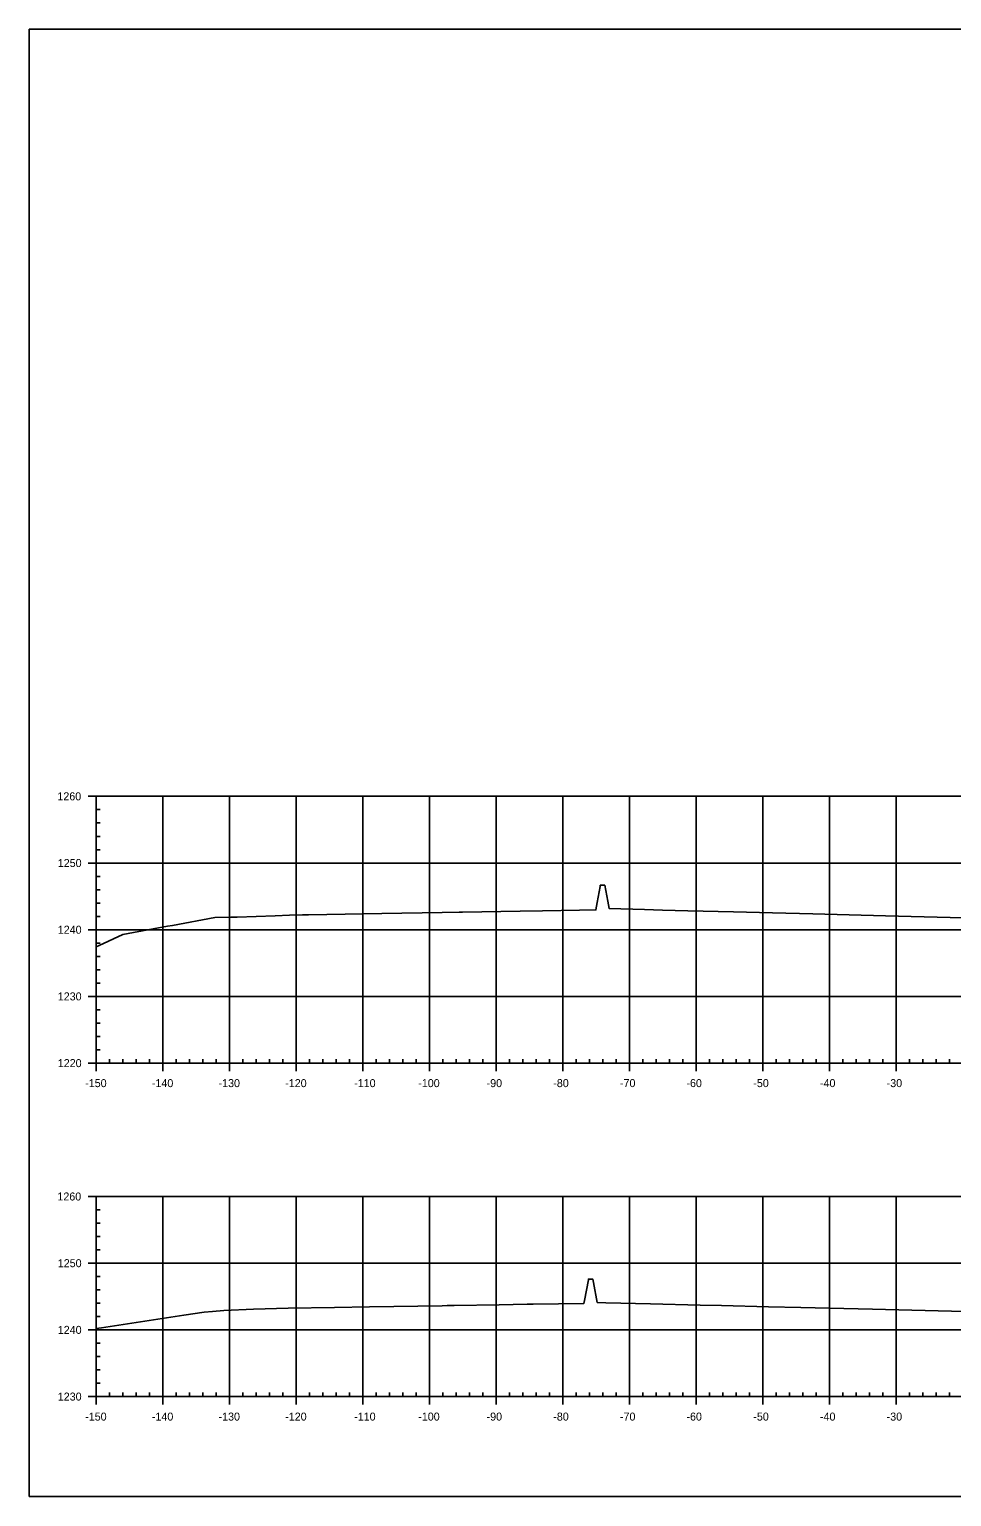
# Model space of a CAD drawing. Extents: x 659657 to 668193, y 633084 to 648639.
# Drawn here: x 667852.5 to 667990.8, y 643502.4 to 643722.4 of the extents above; entities that cross this region are included whole.
import ezdxf

# ---------------------------------------------------------------- set-up
doc = ezdxf.new("R2010")
doc.units = 0
for name, color, linetype in [('R_Axis', 7, 'Continuous'), ('R_Axis Annot', 7, 'Continuous'), ('R_Exist Surface', 7, 'Continuous'), ('R_Grid', 7, 'Continuous'), ('T_SIGNAL CONTROL CABINET', 7, 'Continuous')]:
    doc.layers.add(name, color=color, linetype=linetype)

msp = doc.modelspace()

# ---------------------------------------------------------------- linework, layer by layer
at = {"layer": 'R_Axis'}
for p, q in [((667861.31, 643607.39), (667863.71, 643607.39)), ((667862.51, 643567.39), (667862.51, 643607.39)), ((667862.51, 643605.39), (667863.11, 643605.39)), ((667862.51, 643603.39), (667863.11, 643603.39)), ((667862.51, 643601.39), (667863.11, 643601.39)), ((667862.51, 643599.39), (667863.11, 643599.39)), ((667861.31, 643597.39), (667863.71, 643597.39)), ((667862.51, 643595.39), (667863.11, 643595.39)), ((667862.51, 643593.39), (667863.11, 643593.39)), ((667862.51, 643591.39), (667863.11, 643591.39)), ((667862.51, 643589.39), (667863.11, 643589.39)), ((667861.31, 643587.39), (667863.71, 643587.39)), ((667862.51, 643585.39), (667863.11, 643585.39)), ((667862.51, 643583.39), (667863.11, 643583.39)), ((667862.51, 643581.39), (667863.11, 643581.39)), ((667862.51, 643579.39), (667863.11, 643579.39)), ((667861.31, 643577.39), (667863.71, 643577.39)), ((667862.51, 643575.39), (667863.11, 643575.39)), ((667862.51, 643573.39), (667863.11, 643573.39)), ((667862.51, 643571.39), (667863.11, 643571.39)), ((667862.51, 643569.39), (667863.11, 643569.39)), ((667862.51, 643566.19), (667862.51, 643568.59)), ((667872.51, 643566.19), (667872.51, 643568.59)), ((667882.51, 643566.19), (667882.51, 643568.59)), ((667892.51, 643566.19), (667892.51, 643568.59)), ((667902.51, 643566.19), (667902.51, 643568.59)), ((667912.51, 643566.19), (667912.51, 643568.59)), ((667922.51, 643566.19), (667922.51, 643568.59)), ((667932.51, 643566.19), (667932.51, 643568.59)), ((667942.51, 643566.19), (667942.51, 643568.59)), ((667952.51, 643566.19), (667952.51, 643568.59)), ((667962.51, 643566.19), (667962.51, 643568.59)), ((667972.51, 643566.19), (667972.51, 643568.59)), ((667982.51, 643566.19), (667982.51, 643568.59)), ((667861.31, 643567.39), (667863.71, 643567.39)), ((667862.51, 643567.39), (668162.51, 643567.39)), ((667864.51, 643567.39), (667864.51, 643567.99)), ((667866.51, 643567.39), (667866.51, 643567.99)), ((667868.51, 643567.39), (667868.51, 643567.99)), ((667870.51, 643567.39), (667870.51, 643567.99)), ((667874.51, 643567.39), (667874.51, 643567.99)), ((667876.51, 643567.39), (667876.51, 643567.99)), ((667878.51, 643567.39), (667878.51, 643567.99)), ((667880.51, 643567.39), (667880.51, 643567.99)), ((667884.51, 643567.39), (667884.51, 643567.99)), ((667886.51, 643567.39), (667886.51, 643567.99)), ((667888.51, 643567.39), (667888.51, 643567.99)), ((667890.51, 643567.39), (667890.51, 643567.99)), ((667894.51, 643567.39), (667894.51, 643567.99)), ((667896.51, 643567.39), (667896.51, 643567.99)), ((667898.51, 643567.39), (667898.51, 643567.99)), ((667900.51, 643567.39), (667900.51, 643567.99)), ((667904.51, 643567.39), (667904.51, 643567.99)), ((667906.51, 643567.39), (667906.51, 643567.99)), ((667908.51, 643567.39), (667908.51, 643567.99)), ((667910.51, 643567.39), (667910.51, 643567.99)), ((667914.51, 643567.39), (667914.51, 643567.99)), ((667916.51, 643567.39), (667916.51, 643567.99)), ((667918.51, 643567.39), (667918.51, 643567.99)), ((667920.51, 643567.39), (667920.51, 643567.99)), ((667924.51, 643567.39), (667924.51, 643567.99)), ((667926.51, 643567.39), (667926.51, 643567.99)), ((667928.51, 643567.39), (667928.51, 643567.99)), ((667930.51, 643567.39), (667930.51, 643567.99)), ((667934.51, 643567.39), (667934.51, 643567.99)), ((667936.51, 643567.39), (667936.51, 643567.99)), ((667938.51, 643567.39), (667938.51, 643567.99)), ((667940.51, 643567.39), (667940.51, 643567.99)), ((667944.51, 643567.39), (667944.51, 643567.99)), ((667946.51, 643567.39), (667946.51, 643567.99)), ((667948.51, 643567.39), (667948.51, 643567.99)), ((667950.51, 643567.39), (667950.51, 643567.99)), ((667954.51, 643567.39), (667954.51, 643567.99)), ((667956.51, 643567.39), (667956.51, 643567.99)), ((667958.51, 643567.39), (667958.51, 643567.99)), ((667960.51, 643567.39), (667960.51, 643567.99)), ((667964.51, 643567.39), (667964.51, 643567.99)), ((667966.51, 643567.39), (667966.51, 643567.99)), ((667968.51, 643567.39), (667968.51, 643567.99)), ((667970.51, 643567.39), (667970.51, 643567.99)), ((667974.51, 643567.39), (667974.51, 643567.99)), ((667976.51, 643567.39), (667976.51, 643567.99)), ((667978.51, 643567.39), (667978.51, 643567.99)), ((667980.51, 643567.39), (667980.51, 643567.99)), ((667984.51, 643567.39), (667984.51, 643567.99)), ((667986.51, 643567.39), (667986.51, 643567.99)), ((667988.51, 643567.39), (667988.51, 643567.99)), ((667990.51, 643567.39), (667990.51, 643567.99)), ((667861.31, 643547.39), (667863.71, 643547.39)), ((667862.51, 643517.39), (667862.51, 643547.39)), ((667862.51, 643545.39), (667863.11, 643545.39)), ((667862.51, 643543.39), (667863.11, 643543.39)), ((667862.51, 643541.39), (667863.11, 643541.39)), ((667862.51, 643539.39), (667863.11, 643539.39)), ((667861.31, 643537.39), (667863.71, 643537.39)), ((667862.51, 643535.39), (667863.11, 643535.39)), ((667862.51, 643533.39), (667863.11, 643533.39)), ((667862.51, 643531.39), (667863.11, 643531.39)), ((667862.51, 643529.39), (667863.11, 643529.39)), ((667861.31, 643527.39), (667863.71, 643527.39)), ((667862.51, 643525.39), (667863.11, 643525.39)), ((667862.51, 643523.39), (667863.11, 643523.39)), ((667862.51, 643521.39), (667863.11, 643521.39)), ((667862.51, 643519.39), (667863.11, 643519.39)), ((667862.51, 643516.19), (667862.51, 643518.59)), ((667864.51, 643517.39), (667864.51, 643517.99)), ((667866.51, 643517.39), (667866.51, 643517.99)), ((667868.51, 643517.39), (667868.51, 643517.99)), ((667870.51, 643517.39), (667870.51, 643517.99)), ((667872.51, 643516.19), (667872.51, 643518.59)), ((667874.51, 643517.39), (667874.51, 643517.99)), ((667876.51, 643517.39), (667876.51, 643517.99)), ((667878.51, 643517.39), (667878.51, 643517.99)), ((667880.51, 643517.39), (667880.51, 643517.99)), ((667882.51, 643516.19), (667882.51, 643518.59)), ((667884.51, 643517.39), (667884.51, 643517.99)), ((667886.51, 643517.39), (667886.51, 643517.99)), ((667888.51, 643517.39), (667888.51, 643517.99)), ((667890.51, 643517.39), (667890.51, 643517.99)), ((667892.51, 643516.19), (667892.51, 643518.59)), ((667894.51, 643517.39), (667894.51, 643517.99)), ((667896.51, 643517.39), (667896.51, 643517.99)), ((667898.51, 643517.39), (667898.51, 643517.99)), ((667900.51, 643517.39), (667900.51, 643517.99)), ((667902.51, 643516.19), (667902.51, 643518.59)), ((667904.51, 643517.39), (667904.51, 643517.99)), ((667906.51, 643517.39), (667906.51, 643517.99)), ((667908.51, 643517.39), (667908.51, 643517.99)), ((667910.51, 643517.39), (667910.51, 643517.99)), ((667912.51, 643516.19), (667912.51, 643518.59)), ((667914.51, 643517.39), (667914.51, 643517.99)), ((667916.51, 643517.39), (667916.51, 643517.99)), ((667918.51, 643517.39), (667918.51, 643517.99)), ((667920.51, 643517.39), (667920.51, 643517.99)), ((667922.51, 643516.19), (667922.51, 643518.59)), ((667924.51, 643517.39), (667924.51, 643517.99)), ((667926.51, 643517.39), (667926.51, 643517.99)), ((667928.51, 643517.39), (667928.51, 643517.99)), ((667930.51, 643517.39), (667930.51, 643517.99)), ((667932.51, 643516.19), (667932.51, 643518.59)), ((667934.51, 643517.39), (667934.51, 643517.99)), ((667936.51, 643517.39), (667936.51, 643517.99)), ((667938.51, 643517.39), (667938.51, 643517.99)), ((667940.51, 643517.39), (667940.51, 643517.99)), ((667942.51, 643516.19), (667942.51, 643518.59)), ((667944.51, 643517.39), (667944.51, 643517.99)), ((667946.51, 643517.39), (667946.51, 643517.99)), ((667948.51, 643517.39), (667948.51, 643517.99)), ((667950.51, 643517.39), (667950.51, 643517.99)), ((667952.51, 643516.19), (667952.51, 643518.59)), ((667954.51, 643517.39), (667954.51, 643517.99)), ((667956.51, 643517.39), (667956.51, 643517.99)), ((667958.51, 643517.39), (667958.51, 643517.99)), ((667960.51, 643517.39), (667960.51, 643517.99)), ((667962.51, 643516.19), (667962.51, 643518.59)), ((667964.51, 643517.39), (667964.51, 643517.99)), ((667966.51, 643517.39), (667966.51, 643517.99)), ((667968.51, 643517.39), (667968.51, 643517.99)), ((667970.51, 643517.39), (667970.51, 643517.99)), ((667972.51, 643516.19), (667972.51, 643518.59)), ((667974.51, 643517.39), (667974.51, 643517.99)), ((667976.51, 643517.39), (667976.51, 643517.99)), ((667978.51, 643517.39), (667978.51, 643517.99)), ((667980.51, 643517.39), (667980.51, 643517.99)), ((667982.51, 643516.19), (667982.51, 643518.59)), ((667984.51, 643517.39), (667984.51, 643517.99)), ((667986.51, 643517.39), (667986.51, 643517.99)), ((667988.51, 643517.39), (667988.51, 643517.99)), ((667990.51, 643517.39), (667990.51, 643517.99)), ((667861.31, 643517.39), (667863.71, 643517.39)), ((667862.51, 643517.39), (668162.51, 643517.39))]:
    msp.add_line(p, q, dxfattribs=at)
at = {"layer": 'R_Exist Surface'}
for points in [[(667862.51, 643584.81), (667863, 643585.02), (667866.51, 643586.66), (667871.1, 643587.5), (667873.22, 643587.9), (667873.99, 643588.03), (667880.35, 643589.23), (667882.71, 643589.25), (667883.69, 643589.28), (667889.37, 643589.48), (667891.52, 643589.56), (667893.47, 643589.63), (667894.37, 643589.64), (667905.37, 643589.84), (667914.45, 643589.98), (667916.97, 643590.02), (667917.35, 643590.02), (667917.48, 643590.02), (667926.14, 643590.17), (667929.47, 643590.22), (667935.03, 643590.31), (667937.48, 643590.35), (667937.69, 643591.45), (667938.14, 643593.85), (667938.14, 643593.98), (667938.14, 643594.05), (667938.6, 643594.05), (667938.81, 643594.05), (667938.81, 643594.05), (667938.81, 643594.05), (667939.26, 643591.66), (667939.48, 643590.55), (667944.79, 643590.41), (667947.48, 643590.34), (667951.28, 643590.24), (667958.11, 643590.06), (667963.96, 643589.91), (667970.04, 643589.75), (667970.04, 643589.75), (667980.93, 643589.47), (667994.45, 643589.11)], [(667862.51, 643527.6), (667863.31, 643527.71), (667875.68, 643529.6), (667878.74, 643530.03), (667880, 643530.14), (667881.68, 643530.32), (667886.15, 643530.48), (667891.34, 643530.65), (667898.26, 643530.77), (667903.53, 643530.86), (667914.42, 643531.02), (667915.17, 643531.04), (667915.19, 643531.04), (667915.67, 643531.04), (667916.23, 643531.05), (667922.96, 643531.16), (667927.17, 643531.23), (667927.68, 643531.24), (667928.09, 643531.24), (667935.68, 643531.37), (667935.77, 643531.82), (667936.35, 643534.87), (667936.35, 643534.98), (667936.35, 643535), (667936.92, 643535), (667937.02, 643535), (667937.02, 643535), (667937.02, 643535), (667937.11, 643534.5), (667937.69, 643531.5), (667938.97, 643531.46), (667945.69, 643531.3), (667953.1, 643531.12), (667956.33, 643531.04), (667963.39, 643530.86), (667968.21, 643530.74), (667978.95, 643530.48), (667992.75, 643530.14)]]:
    msp.add_lwpolyline(points, dxfattribs=at)
at = {"layer": 'R_Grid'}
for p, q in [((667862.51, 643607.39), (668162.51, 643607.39)), ((667862.51, 643567.39), (667862.51, 643607.39)), ((667872.51, 643567.39), (667872.51, 643607.39)), ((667882.51, 643567.39), (667882.51, 643607.39)), ((667892.51, 643567.39), (667892.51, 643607.39)), ((667902.51, 643567.39), (667902.51, 643607.39)), ((667912.51, 643567.39), (667912.51, 643607.39)), ((667922.51, 643567.39), (667922.51, 643607.39)), ((667932.51, 643567.39), (667932.51, 643607.39)), ((667942.51, 643567.39), (667942.51, 643607.39)), ((667952.51, 643567.39), (667952.51, 643607.39)), ((667962.51, 643567.39), (667962.51, 643607.39)), ((667972.51, 643567.39), (667972.51, 643607.39)), ((667982.51, 643567.39), (667982.51, 643607.39)), ((667862.51, 643597.39), (668162.51, 643597.39)), ((667862.51, 643587.39), (668162.51, 643587.39)), ((667862.51, 643577.39), (668162.51, 643577.39)), ((667862.51, 643567.39), (668162.51, 643567.39)), ((667862.51, 643547.39), (668162.51, 643547.39)), ((667862.51, 643517.39), (667862.51, 643547.39)), ((667872.51, 643517.39), (667872.51, 643547.39)), ((667882.51, 643517.39), (667882.51, 643547.39)), ((667892.51, 643517.39), (667892.51, 643547.39)), ((667902.51, 643517.39), (667902.51, 643547.39)), ((667912.51, 643517.39), (667912.51, 643547.39)), ((667922.51, 643517.39), (667922.51, 643547.39)), ((667932.51, 643517.39), (667932.51, 643547.39)), ((667942.51, 643517.39), (667942.51, 643547.39)), ((667952.51, 643517.39), (667952.51, 643547.39)), ((667962.51, 643517.39), (667962.51, 643547.39)), ((667972.51, 643517.39), (667972.51, 643547.39)), ((667982.51, 643517.39), (667982.51, 643547.39)), ((667862.51, 643537.39), (668162.51, 643537.39)), ((667862.51, 643527.39), (668162.51, 643527.39)), ((667862.51, 643517.39), (668162.51, 643517.39))]:
    msp.add_line(p, q, dxfattribs=at)
at = {"layer": 'T_SIGNAL CONTROL CABINET'}
msp.add_lwpolyline([(667852.51, 643502.39), (668192.51, 643502.39), (668192.51, 643722.39), (667852.51, 643722.39)], close=True, dxfattribs=at)

# ---------------------------------------------------------------- texts
at = {"layer": 'R_Axis Annot'}
for s, p in [('1260', (667856.72, 643606.79)), ('1250', (667856.78, 643596.79)), ('1240', (667856.78, 643586.79)), ('1230', (667856.78, 643576.79)), ('1220', (667856.78, 643566.79)), ('-150', (667860.89, 643563.79)), ('-140', (667870.89, 643563.79)), ('-130', (667880.89, 643563.79)), ('-120', (667890.89, 643563.79)), ('-110', (667901.23, 643563.79)), ('-100', (667910.84, 643563.79)), ('-90', (667921.09, 643563.79)), ('-80', (667931.09, 643563.79)), ('-70', (667941.09, 643563.79)), ('-60', (667951.06, 643563.79)), ('-50', (667961.09, 643563.79)), ('-40', (667971.09, 643563.79)), ('-30', (667981.09, 643563.79)), ('1260', (667856.72, 643546.79)), ('1250', (667856.78, 643536.79)), ('1240', (667856.78, 643526.79)), ('1230', (667856.78, 643516.79)), ('-150', (667860.89, 643513.79)), ('-140', (667870.89, 643513.79)), ('-130', (667880.89, 643513.79)), ('-120', (667890.89, 643513.79)), ('-110', (667901.23, 643513.79)), ('-100', (667910.84, 643513.79)), ('-90', (667921.09, 643513.79)), ('-80', (667931.09, 643513.79)), ('-70', (667941.09, 643513.79)), ('-60', (667951.06, 643513.79)), ('-50', (667961.09, 643513.79)), ('-40', (667971.09, 643513.79)), ('-30', (667981.09, 643513.79))]:
    msp.add_text(s, height=1.2, dxfattribs=at).set_placement(p)

doc.saveas('drawing.dxf')
